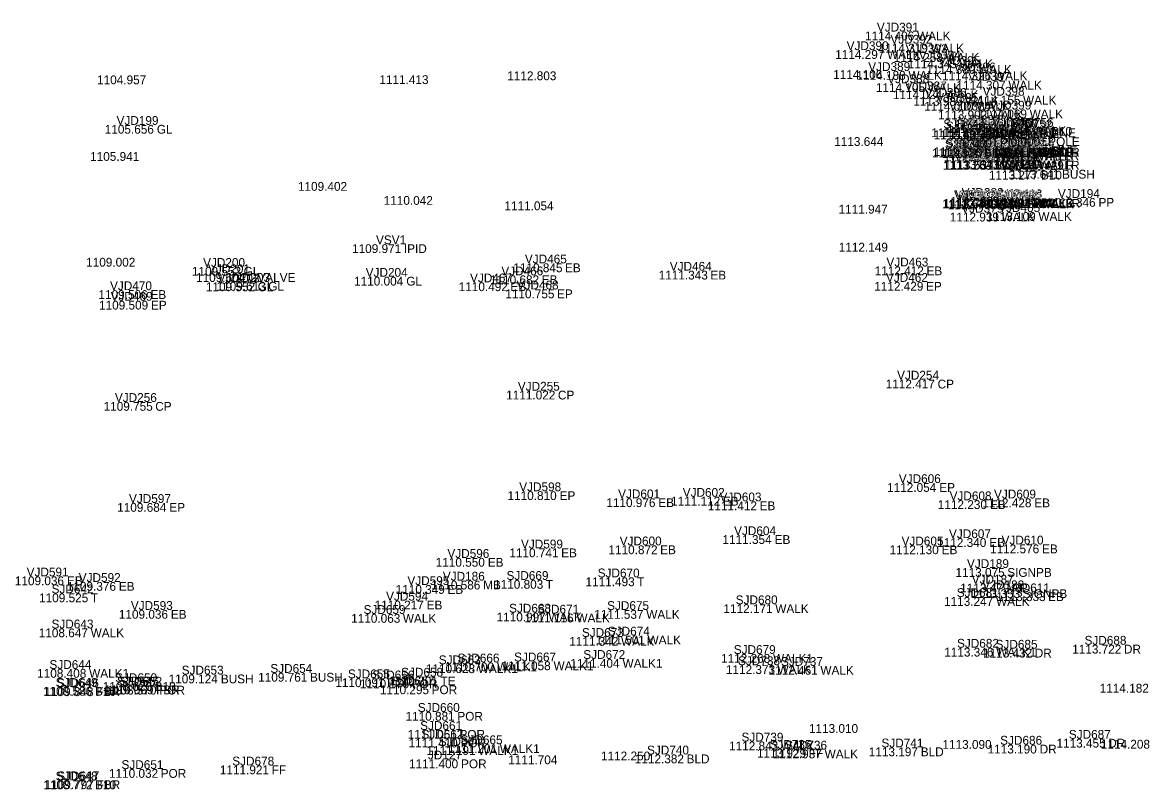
# Model space of a CAD drawing. Extents: x 1629927 to 1630657, y 484405 to 484576.
# Drawn here: x 1630425.4 to 1630553.3, y 484451 to 484538 of the extents above; entities that cross this region are included whole.
import ezdxf

# ---------------------------------------------------------------- set-up
doc = ezdxf.new("R2010")
doc.units = 0
for name, color, linetype in [('SV_X_Text_Comment', 7, 'Continuous'), ('SV_X_Text_Elevation', 7, 'Continuous'), ('SV_X_Text_Name', 7, 'Continuous')]:
    doc.layers.add(name, color=color, linetype=linetype)

msp = doc.modelspace()

# ---------------------------------------------------------------- texts
at = {"layer": 'SV_X_Text_Comment'}
for s, p in [('WALK', (1630526.9, 484535.95)), ('WALK', (1630523.5, 484533.84)), ('WALK', (1630528.43, 484534.57)), ('WALK', (1630530.15, 484533.5)), ('WALK', (1630531.71, 484532.79)), ('WALK', (1630525.92, 484531.47)), ('WALK', (1630533.85, 484532.15)), ('WALK', (1630535.63, 484531.43)), ('WALK', (1630528.1, 484530.09)), ('WALK', (1630537.26, 484530.36)), ('WALK', (1630530.08, 484529.28)), ('WALK', (1630532.35, 484528.53)), ('WALK', (1630538.92, 484528.67)), ('WALK', (1630533.63, 484527.96)), ('WALK', (1630535.15, 484526.99)), ('WALK', (1630539.67, 484527.1)), ('GL', (1630440.64, 484525.36)), ('B10', (1630534.38, 484524.97)), ('LINE', (1630534.65, 484524.73)), ('B10', (1630535.72, 484524.99)), ('WALK', (1630536.15, 484525.45)), ('WALK', (1630536.49, 484524.76)), ('LINE', (1630536.46, 484524.75)), ('WALK', (1630540.03, 484525.18)), ('LINE', (1630540.03, 484524.86)), ('B10', (1630540.34, 484525.04)), ('LINE', (1630541.94, 484524.95)), ('B10', (1630542.11, 484525.13)), ('LPOLE', (1630535.57, 484523.81)), ('LPOLE', (1630541.04, 484523.96)), ('B10', (1630534.49, 484522.68)), ('LINE', (1630534.63, 484522.82)), ('B10', (1630535.63, 484522.6)), ('B10', (1630535.63, 484522.59)), ('WALLR', (1630535.76, 484522.72)), ('WALLR', (1630535.78, 484522.22)), ('WALLR', (1630536.37, 484522.69)), ('WALLR', (1630536.4, 484522.24)), ('WALK', (1630536.6, 484522.72)), ('WALK', (1630536.62, 484522.91)), ('LINE', (1630536.54, 484522.85)), ('WALK', (1630539.86, 484523.07)), ('WALK', (1630539.99, 484522.76)), ('WALLR', (1630540.11, 484522.31)), ('WALLR', (1630540.14, 484522.74)), ('LINE', (1630540.12, 484522.94)), ('WALLR', (1630540.69, 484522.33)), ('WALLR', (1630540.73, 484522.77)), ('B10', (1630540.85, 484522.71)), ('B10', (1630541.1, 484522.82)), ('LINE', (1630542.11, 484523.01)), ('B10', (1630542.17, 484522.86)), ('B10', (1630535.69, 484521.27)), ('WALLR', (1630535.88, 484521.29)), ('WALLR', (1630536.51, 484521.36)), ('WALLR', (1630540.14, 484521.3)), ('WALLR', (1630540.73, 484521.28)), ('B10', (1630540.95, 484520.16)), ('BUSH', (1630543.35, 484520.26)), ('WALLR', (1630535.8, 484516.97)), ('WALK', (1630536.56, 484517.19)), ('B10', (1630540.92, 484517.03)), ('PP', (1630547.48, 484517.07)), ('B10', (1630535.67, 484516.9)), ('B10', (1630536.25, 484516.79)), ('WALLR', (1630536.42, 484516.94)), ('WALK', (1630540.05, 484516.94)), ('WALLR', (1630540.14, 484516.94)), ('WALLR', (1630540.81, 484516.96)), ('WALK', (1630540.89, 484516.89)), ('WALK', (1630536.49, 484515.4)), ('WALK', (1630540.66, 484515.47)), ('IPID', (1630468.67, 484511.82)), ('EB', (1630486.95, 484509.65)), ('EB', (1630527.97, 484509.3)), ('GL', (1630450.49, 484509.25)), ('GVALVE', (1630451.01, 484508.54)), ('GL', (1630468.94, 484508.13)), ('EB', (1630484.31, 484508.29)), ('EB', (1630503.45, 484508.82)), ('GL', (1630452.08, 484507.49)), ('GL', (1630453.28, 484507.55)), ('EB', (1630480.76, 484507.5)), ('EP', (1630527.92, 484507.55)), ('EB', (1630439.92, 484506.61)), ('EP', (1630486.05, 484506.69)), ('EP', (1630439.97, 484505.41)), ('CP', (1630529.23, 484496.46)), ('CP', (1630440.46, 484493.93)), ('CP', (1630486.15, 484495.21)), ('EP', (1630486.34, 484483.8)), ('EP', (1630529.42, 484484.73)), ('EP', (1630442.06, 484482.47)), ('EB', (1630497.54, 484483)), ('EB', (1630504.86, 484483.17)), ('EB', (1630509.03, 484482.65)), ('EB', (1630535.17, 484482.78)), ('EB', (1630540.2, 484482.98)), ('EB', (1630510.74, 484478.82)), ('EB', (1630497.75, 484477.66)), ('EB', (1630529.69, 484477.66)), ('EB', (1630535.09, 484478.48)), ('EB', (1630541.08, 484477.76)), ('EB', (1630478.19, 484476.24)), ('EB', (1630486.52, 484477.31)), ('SIGNPB', (1630537.13, 484475.09)), ('EB', (1630430.44, 484474.14)), ('EB', (1630436.33, 484473.51)), ('MB', (1630477.67, 484473.66)), ('T', (1630484.77, 484473.74)), ('T', (1630495.14, 484474.03)), ('EB', (1630473.62, 484473.16)), ('PP', (1630537.67, 484473.32)), ('SIGNPB', (1630538.88, 484472.68)), ('EB', (1630541.77, 484472.34)), ('T', (1630433.15, 484472.21)), ('EB', (1630471.25, 484471.39)), ('WALK', (1630510.81, 484470.98)), ('WALK', (1630535.86, 484471.8)), ('EB', (1630442.23, 484470.34)), ('WALK', (1630468.55, 484469.88)), ('WALK', (1630485.08, 484470.03)), ('WALK', (1630488.25, 484469.92)), ('WALK', (1630496.17, 484470.33)), ('WALK', (1630433.13, 484468.24)), ('WALK', (1630493.31, 484467.27)), ('WALK', (1630496.32, 484467.43)), ('WALK1', (1630535.88, 484466.05)), ('DR', (1630540.25, 484465.94)), ('DR', (1630550.37, 484466.39)), ('WALK1', (1630493.48, 484464.78)), ('WALK1', (1630510.56, 484465.34)), ('WALK1', (1630432.96, 484463.64)), ('WALK1', (1630477.06, 484464.17)), ('WALK1', (1630479.24, 484464.38)), ('WALK1', (1630485.65, 484464.5)), ('WALK', (1630511.07, 484464.07)), ('WALK', (1630515.93, 484463.99)), ('B10', (1630440.4, 484462.15)), ('BUSH', (1630447.9, 484463.01)), ('BUSH', (1630458.02, 484463.2)), ('POR', (1630466.77, 484462.58)), ('POR', (1630469.58, 484462.46)), ('TE', (1630472.83, 484462.77)), ('B10', (1630433.62, 484461.61)), ('FBR', (1630433.78, 484461.56)), ('FBR', (1630440.56, 484461.77)), ('POR', (1630440.93, 484461.74)), ('POR', (1630471.82, 484461.78)), ('POR', (1630474.74, 484458.77)), ('POR', (1630474.98, 484456.72)), ('POR', (1630475.11, 484455.74)), ('DR', (1630548.59, 484455.72)), ('WALK1', (1630477.11, 484454.89)), ('WALK1', (1630479.55, 484455.1)), ('WALK', (1630511.44, 484455.41)), ('FF', (1630514.61, 484454.59)), ('WALK', (1630516.41, 484454.5)), ('BLD', (1630527.32, 484454.74)), ('DR', (1630540.81, 484455.05)), ('POR', (1630475.16, 484453.38)), ('BLD', (1630500.75, 484453.94)), ('POR', (1630441.08, 484452.29)), ('FF', (1630453.67, 484452.69)), ('B10', (1630433.63, 484450.99)), ('FBR', (1630433.81, 484451.01))]:
    msp.add_text(s, height=1, dxfattribs=at).set_placement(p)
at = {"layer": 'SV_X_Text_Elevation'}
for s, p in [('1114.406', (1630521, 484535.95)), ('1114.297', (1630517.61, 484533.84)), ('1114.319', (1630522.55, 484534.57)), ('1114.258', (1630524.25, 484533.5)), ('1114.345', (1630525.84, 484532.79)), ('1112.803', (1630480.4, 484531.43)), ('1114.106', (1630517.38, 484531.58)), ('1114.188', (1630520.02, 484531.47)), ('1114.380', (1630527.94, 484532.15)), ('1114.326', (1630529.73, 484531.43)), ('1104.957', (1630433.86, 484530.97)), ('1111.413', (1630465.89, 484530.99)), ('1114.105', (1630522.23, 484530.09)), ('1114.307', (1630531.37, 484530.36)), ('1114.024', (1630524.16, 484529.28)), ('1113.989', (1630526.47, 484528.53)), ('1114.155', (1630533.05, 484528.67)), ('1114.000', (1630527.71, 484527.96)), ('1113.902', (1630529.28, 484526.99)), ('1114.069', (1630533.79, 484527.1)), ('1105.656', (1630434.73, 484525.36)), ('1113.712', (1630528.51, 484524.97)), ('1115.685', (1630528.78, 484524.73)), ('1113.710', (1630529.81, 484524.99)), ('1113.753', (1630530.29, 484525.45)), ('1115.684', (1630530.54, 484524.75)), ('1113.700', (1630530.58, 484524.76)), ('1115.787', (1630534.13, 484524.86)), ('1113.841', (1630534.15, 484525.18)), ('1113.709', (1630534.45, 484525.04)), ('1115.786', (1630536.04, 484524.95)), ('1113.836', (1630536.21, 484525.13)), ('1113.644', (1630517.5, 484523.97)), ('0.000', (1630532.06, 484523.81)), ('0.000', (1630537.52, 484523.96)), ('1105.941', (1630433.07, 484522.28)), ('1113.526', (1630528.59, 484522.68)), ('1115.695', (1630528.77, 484522.82)), ('1113.370', (1630529.72, 484522.59)), ('1113.346', (1630529.73, 484522.6)), ('1114.355', (1630529.89, 484522.72)), ('1114.255', (1630529.91, 484522.22)), ('1114.344', (1630530.45, 484522.69)), ('1114.271', (1630530.52, 484522.24)), ('1115.689', (1630530.66, 484522.85)), ('1113.042', (1630530.72, 484522.72)), ('1113.583', (1630530.76, 484522.91)), ('1113.769', (1630533.98, 484523.07)), ('1113.241', (1630534.11, 484522.76)), ('1114.267', (1630534.21, 484522.31)), ('1115.775', (1630534.25, 484522.94)), ('1114.409', (1630534.25, 484522.74)), ('1114.445', (1630534.82, 484522.33)), ('1114.387', (1630534.83, 484522.77)), ('1113.495', (1630534.98, 484522.71)), ('1113.498', (1630535.2, 484522.82)), ('1115.793', (1630536.25, 484523.01)), ('1113.628', (1630536.27, 484522.86)), ('1113.263', (1630529.83, 484521.27)), ('1113.637', (1630529.99, 484521.29)), ('1113.643', (1630530.65, 484521.36)), ('1113.775', (1630534.27, 484521.3)), ('1113.844', (1630534.8, 484521.28)), ('1113.277', (1630535.05, 484520.16)), ('1113.641', (1630537.47, 484520.26)), ('1109.402', (1630456.65, 484518.88)), ('1110.042', (1630466.38, 484517.29)), ('1113.360', (1630529.89, 484516.97)), ('1112.889', (1630530.68, 484517.19)), ('1113.837', (1630534.91, 484516.96)), ('1112.947', (1630535.03, 484517.03)), ('1113.346', (1630541.58, 484517.07)), ('1111.054', (1630480.08, 484516.68)), ('1111.947', (1630517.99, 484516.29)), ('1112.634', (1630529.75, 484516.9)), ('1112.765', (1630530.38, 484516.79)), ('1113.410', (1630530.5, 484516.94)), ('1113.034', (1630534.13, 484516.94)), ('1113.822', (1630534.27, 484516.94)), ('1113.049', (1630535.01, 484516.89)), ('1112.939', (1630530.61, 484515.4)), ('1113.109', (1630534.78, 484515.47)), ('1112.149', (1630518.01, 484511.99)), ('1109.971', (1630462.79, 484511.82)), ('1109.002', (1630432.62, 484510.28)), ('1110.845', (1630481.09, 484509.65)), ('1112.412', (1630522.09, 484509.3)), ('1109.552', (1630444.62, 484509.25)), ('1109.604', (1630445.09, 484508.54)), ('1110.004', (1630463.02, 484508.13)), ('1110.682', (1630478.44, 484508.29)), ('1111.343', (1630497.58, 484508.82)), ('1109.552', (1630446.21, 484507.49)), ('1109.613', (1630447.42, 484507.55)), ('1110.492', (1630474.89, 484507.5)), ('1112.429', (1630522.04, 484507.55)), ('1109.506', (1630434.02, 484506.61)), ('1110.755', (1630480.18, 484506.69)), ('1109.509', (1630434.08, 484505.41)), ('1112.417', (1630523.34, 484496.46)), ('1109.755', (1630434.6, 484493.93)), ('1111.022', (1630480.28, 484495.21)), ('1110.810', (1630480.43, 484483.8)), ('1112.054', (1630523.5, 484484.73)), ('1109.684', (1630436.14, 484482.47)), ('1110.976', (1630491.64, 484483)), ('1111.112', (1630498.99, 484483.17)), ('1111.412', (1630503.16, 484482.65)), ('1112.230', (1630529.25, 484482.78)), ('1112.428', (1630534.3, 484482.98)), ('1111.354', (1630504.82, 484478.82)), ('1110.741', (1630480.64, 484477.31)), ('1110.872', (1630491.88, 484477.66)), ('1112.130', (1630523.78, 484477.66)), ('1112.340', (1630529.18, 484478.48)), ('1112.576', (1630535.18, 484477.76)), ('1110.550', (1630472.28, 484476.24)), ('1113.075', (1630531.26, 484475.09)), ('1109.036', (1630424.53, 484474.14)), ('1109.376', (1630430.43, 484473.51)), ('1110.586', (1630471.77, 484473.66)), ('1110.803', (1630478.91, 484473.74)), ('1111.493', (1630489.28, 484474.03)), ('1109.525', (1630427.28, 484472.21)), ('1110.349', (1630467.74, 484473.16)), ('1113.479', (1630531.79, 484473.32)), ('1113.353', (1630533.01, 484472.68)), ('1113.333', (1630535.91, 484472.34)), ('1110.217', (1630465.35, 484471.39)), ('1112.171', (1630504.93, 484470.98)), ('1113.247', (1630529.96, 484471.8)), ('1109.036', (1630436.33, 484470.34)), ('1110.063', (1630462.69, 484469.88)), ('1110.997', (1630479.19, 484470.03)), ('1111.116', (1630482.35, 484469.92)), ('1111.537', (1630490.28, 484470.33)), ('1108.647', (1630427.24, 484468.24)), ('1111.342', (1630487.43, 484467.27)), ('1111.501', (1630490.44, 484467.43)), ('1113.346', (1630529.98, 484466.05)), ('1113.432', (1630534.38, 484465.94)), ('1113.722', (1630544.5, 484466.39)), ('1111.404', (1630487.56, 484464.78)), ('1112.268', (1630504.66, 484465.34)), ('1108.408', (1630427.06, 484463.64)), ('1110.628', (1630471.17, 484464.17)), ('1110.700', (1630473.33, 484464.38)), ('1111.058', (1630479.75, 484464.5)), ('1112.373', (1630505.21, 484464.07)), ('1112.461', (1630510.05, 484463.99)), ('1108.626', (1630434.5, 484462.15)), ('1109.124', (1630441.98, 484463.01)), ('1109.761', (1630452.14, 484463.2)), ('1110.091', (1630460.89, 484462.58)), ('1110.176', (1630463.68, 484462.46)), ('1110.301', (1630466.95, 484462.77)), ('1108.586', (1630427.72, 484461.61)), ('1109.848', (1630427.88, 484461.56)), ('1110.069', (1630434.68, 484461.77)), ('1108.570', (1630435.02, 484461.74)), ('1110.295', (1630465.95, 484461.78)), ('1114.182', (1630547.62, 484461.96)), ('1110.881', (1630468.86, 484458.77)), ('1113.010', (1630514.63, 484457.39)), ('1111.051', (1630469.1, 484456.72)), ('1111.410', (1630469.2, 484455.74)), ('1113.090', (1630529.78, 484455.58)), ('1113.455', (1630542.72, 484455.72)), ('1114.208', (1630547.75, 484455.6)), ('1111.191', (1630471.23, 484454.89)), ('1111.201', (1630473.67, 484455.1)), ('1112.843', (1630505.57, 484455.41)), ('1113.929', (1630508.73, 484454.59)), ('1112.937', (1630510.51, 484454.5)), ('1113.197', (1630521.42, 484454.74)), ('1113.190', (1630534.9, 484455.05)), ('1111.400', (1630469.25, 484453.38)), ('1111.704', (1630480.51, 484453.83)), ('1112.250', (1630491.04, 484454.27)), ('1112.382', (1630494.87, 484453.94)), ('1110.032', (1630435.21, 484452.29)), ('1111.921', (1630447.79, 484452.69)), ('1108.772', (1630427.76, 484450.99)), ('1109.797', (1630427.91, 484451.01))]:
    msp.add_text(s, height=1, dxfattribs=at).set_placement(p)
at = {"layer": 'SV_X_Text_Name'}
for s, p in [('VJD391', (1630522.34, 484536.95)), ('VJD392', (1630523.88, 484535.57)), ('VJD390', (1630518.91, 484534.84)), ('VJD393', (1630525.6, 484534.5)), ('VJD394', (1630527.1, 484533.79)), ('VJD389', (1630521.36, 484532.47)), ('VJD395', (1630529.3, 484533.15)), ('VJD396', (1630531.05, 484532.43)), ('VJD388', (1630523.52, 484531.09)), ('VJD397', (1630532.68, 484531.36)), ('VJD387', (1630525.5, 484530.28)), ('VJD386', (1630527.77, 484529.53)), ('VJD385', (1630529.08, 484528.96)), ('VJD398', (1630534.34, 484529.67)), ('VJD384', (1630530.55, 484527.99)), ('VJD399', (1630535.1, 484528.1)), ('VJD199', (1630436.07, 484526.36)), ('SJD744', (1630529.88, 484525.97)), ('SJD745', (1630531.28, 484525.99)), ('VJD383', (1630531.61, 484526.45)), ('VJD400', (1630535.44, 484526.18)), ('SJD757', (1630535.87, 484526.04)), ('SJD752', (1630537.49, 484525.95)), ('SJD756', (1630537.63, 484526.13)), ('SJD747', (1630530.18, 484525.73)), ('JD126', (1630531.8, 484524.81)), ('SJD746', (1630531.98, 484525.75)), ('JD100', (1630532.71, 484525.76)), ('SJD751', (1630535.57, 484525.86)), ('JD125', (1630537.3, 484524.96)), ('SJD743', (1630530.05, 484523.68)), ('SJD748', (1630530.16, 484523.82)), ('VJD414', (1630531.03, 484523.59)), ('VJD410', (1630531.17, 484523.72)), ('SJD742', (1630531.19, 484523.6)), ('VJD411', (1630531.81, 484523.69)), ('VJD381', (1630532.03, 484523.72)), ('VJD382', (1630532.07, 484523.91)), ('SJD749', (1630532.08, 484523.85)), ('VJD401', (1630535.3, 484524.07)), ('VJD402', (1630535.43, 484523.76)), ('VJD422', (1630535.58, 484523.74)), ('SJD750', (1630535.63, 484523.94)), ('VJD421', (1630536.17, 484523.77)), ('VJD420', (1630536.26, 484523.71)), ('SJD754', (1630536.6, 484523.82)), ('SJD753', (1630537.67, 484524.01)), ('SJD755', (1630537.73, 484523.86)), ('VJD415', (1630531.14, 484522.27)), ('VJD409', (1630531.21, 484523.22)), ('VJD408', (1630531.3, 484522.29)), ('VJD412', (1630531.85, 484523.24)), ('VJD413', (1630531.97, 484522.36)), ('VJD424', (1630535.54, 484522.3)), ('VJD423', (1630535.56, 484523.31)), ('VJD428', (1630536.11, 484523.33)), ('VJD427', (1630536.15, 484522.28)), ('VJD419', (1630536.38, 484521.16)), ('VJD429', (1630538.79, 484521.26)), ('VJD416', (1630531.09, 484517.9)), ('VJD407', (1630531.23, 484517.97)), ('VJD417', (1630531.68, 484517.79)), ('VJD406', (1630531.83, 484517.94)), ('VJD380', (1630531.96, 484518.19)), ('VJD403', (1630535.51, 484517.94)), ('VJD425', (1630535.59, 484517.94)), ('VJD426', (1630536.22, 484517.96)), ('VJD404', (1630536.29, 484517.89)), ('VJD418', (1630536.34, 484518.03)), ('VJD194', (1630542.88, 484518.07)), ('VJD379', (1630531.92, 484516.4)), ('VJD405', (1630536.11, 484516.47)), ('VSV1', (1630465.51, 484512.82)), ('VJD465', (1630482.4, 484510.65)), ('VJD200', (1630445.89, 484510.25)), ('VJD201', (1630446.45, 484509.54)), ('VJD466', (1630479.73, 484509.29)), ('VJD464', (1630498.84, 484509.82)), ('VJD463', (1630523.42, 484510.3)), ('VJD202', (1630447.53, 484508.49)), ('VJD203', (1630448.73, 484508.55)), ('VJD204', (1630464.34, 484509.13)), ('VJD467', (1630476.18, 484508.5)), ('VJD462', (1630523.37, 484508.55)), ('VJD470', (1630435.33, 484507.61)), ('VJD468', (1630481.47, 484507.69)), ('VJD469', (1630435.4, 484506.41)), ('VJD254', (1630524.63, 484497.46)), ('VJD255', (1630481.6, 484496.21)), ('VJD256', (1630435.88, 484494.93)), ('VJD606', (1630524.83, 484485.73)), ('VJD598', (1630481.76, 484484.8)), ('VJD601', (1630492.98, 484484)), ('VJD602', (1630500.31, 484484.17)), ('VJD608', (1630530.59, 484483.78)), ('VJD609', (1630535.63, 484483.98)), ('VJD597', (1630437.48, 484483.47)), ('VJD603', (1630504.49, 484483.65)), ('VJD600', (1630493.16, 484478.66)), ('VJD604', (1630506.14, 484479.82)), ('VJD605', (1630525.14, 484478.66)), ('VJD607', (1630530.52, 484479.48)), ('VJD610', (1630536.49, 484478.76)), ('VJD599', (1630481.96, 484478.31)), ('VJD596', (1630473.61, 484477.24)), ('VJD189', (1630532.56, 484476.09)), ('VJD591', (1630425.87, 484475.14)), ('SJD670', (1630490.66, 484475.03)), ('VJD592', (1630431.78, 484474.51)), ('VJD595', (1630469.07, 484474.16)), ('VJD186', (1630473.09, 484474.66)), ('SJD669', (1630480.32, 484474.74)), ('VJD187', (1630533.1, 484474.32)), ('VJD188', (1630534.3, 484473.68)), ('SJD642', (1630428.7, 484473.21)), ('VJD594', (1630466.65, 484472.39)), ('SJD681', (1630531.4, 484472.8)), ('VJD611', (1630537.21, 484473.34)), ('VJD593', (1630437.69, 484471.34)), ('SJD668', (1630480.61, 484471.03)), ('SJD671', (1630483.8, 484470.92)), ('SJD675', (1630491.73, 484471.33)), ('SJD680', (1630506.32, 484471.98)), ('SJD659', (1630464.1, 484470.88)), ('SJD643', (1630428.69, 484469.24)), ('SJD674', (1630491.82, 484468.43)), ('SJD673', (1630488.87, 484468.27)), ('SJD688', (1630545.9, 484467.39)), ('SJD679', (1630506.1, 484466.34)), ('SJD682', (1630531.43, 484467.05)), ('SJD685', (1630535.81, 484466.94)), ('SJD644', (1630428.46, 484464.64)), ('SJD663', (1630472.63, 484465.17)), ('SJD666', (1630474.76, 484465.38)), ('SJD667', (1630481.18, 484465.5)), ('SJD672', (1630489.03, 484465.78)), ('SJD738', (1630506.59, 484465.07)), ('SJD737', (1630511.46, 484464.99)), ('SJD653', (1630443.46, 484464.01)), ('SJD654', (1630453.52, 484464.2)), ('SJD655', (1630462.32, 484463.58)), ('SJD656', (1630465.1, 484463.46)), ('SJD658', (1630468.36, 484463.77)), ('SJD649', (1630429.16, 484462.61)), ('SJD646', (1630429.3, 484462.56)), ('SJD650', (1630435.91, 484463.15)), ('SJD645', (1630436.12, 484462.77)), ('SJD652', (1630436.48, 484462.74)), ('SJD657', (1630467.35, 484462.78)), ('SJD660', (1630470.25, 484459.77)), ('SJD661', (1630470.52, 484457.72)), ('SJD662', (1630470.66, 484456.74)), ('SJD664', (1630472.62, 484455.89)), ('SJD665', (1630475.11, 484456.1)), ('SJD739', (1630506.98, 484456.41)), ('SJD735', (1630510.16, 484455.59)), ('SJD741', (1630522.86, 484455.74)), ('SJD686', (1630536.33, 484456.05)), ('SJD687', (1630544.12, 484456.72)), ('JD127', (1630471.4, 484454.38)), ('SJD740', (1630496.26, 484454.94)), ('SJD736', (1630511.93, 484455.5)), ('SJD651', (1630436.63, 484453.29)), ('SJD678', (1630449.2, 484453.69)), ('SJD648', (1630429.16, 484451.99)), ('SJD647', (1630429.34, 484452.01))]:
    msp.add_text(s, height=1, dxfattribs=at).set_placement(p)

doc.saveas('drawing.dxf')
